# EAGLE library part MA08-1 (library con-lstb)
PIN HEADER
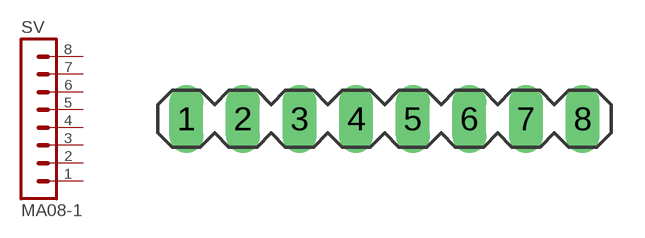
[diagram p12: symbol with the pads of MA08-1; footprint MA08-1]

Designator prefix SV

## MA08-1 (OC_FARNELL: unknown; OC_NEWARK: unknown)  [MA08-1]
1  1  pas
2  2  pas
3  3  pas
4  4  pas
5  5  pas
6  6  pas
7  7  pas
8  8  pas

## Footprint MA08-1 (pad centres in mm)
PIN HEADER
drill 1.016 long: 1 -8.89,0; 2 -6.35,0; 3 -3.81,0; 4 -1.27,0; 5 1.27,0; 6 3.81,0; 7 6.35,0; 8 8.89,0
